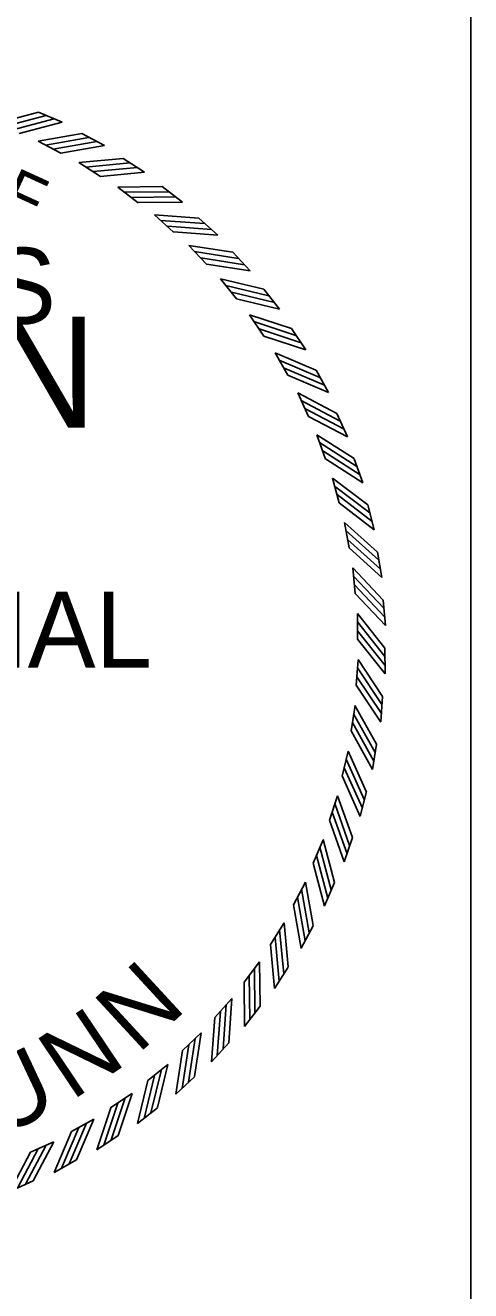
# Model space of a CAD drawing. Extents: x 0 to 1228740, y 0 to 152440.
# Drawn here: x 32.511 to 33.423, y 17.743 to 20.334 of the extents above; entities that cross this region are included whole.
import ezdxf

# ---------------------------------------------------------------- set-up
doc = ezdxf.new("R2010")
doc.units = 0
for name, color, linetype in [('R_Border', 7, 'Continuous'), ('R_Draft', 7, 'Continuous'), ('STAMP', 7, 'Continuous')]:
    doc.layers.add(name, color=color, linetype=linetype)

msp = doc.modelspace()

# ---------------------------------------------------------------- linework, layer by layer
at = {"layer": 'R_Border'}
msp.add_line((33.4231, 0.5768), (33.4231, 21.4232), dxfattribs=at)
at = {"layer": 'STAMP'}
for p, q in [((32.5379, 20.1563), (32.5861, 20.1357)), ((32.6265, 20.1125), (32.6728, 20.088)), ((32.5372, 20.0967), (32.5836, 20.0721)), ((32.7111, 20.0615), (32.7552, 20.0332)), ((32.6208, 20.0531), (32.665, 20.0248)), ((32.7005, 20.0028), (32.7422, 19.9709)), ((32.7912, 20.0037), (32.8328, 19.9719)), ((32.7758, 19.946), (32.8147, 19.9108)), ((32.8662, 19.9395), (32.9051, 19.9043)), ((32.8461, 19.8833), (32.882, 19.845)), ((32.9357, 19.8693), (32.9716, 19.831)), ((32.911, 19.8149), (32.9437, 19.7738)), ((32.9992, 19.7936), (33.0317, 19.7525)), ((32.9701, 19.7415), (32.9992, 19.6978)), ((33.0562, 19.7129), (33.0852, 19.6693)), ((33.0229, 19.6634), (33.0483, 19.6174)), ((33.1063, 19.6278), (33.1316, 19.5819)), ((33.069, 19.5812), (33.0906, 19.5333)), ((33.1492, 19.5388), (33.1707, 19.491)), ((33.1082, 19.4954), (33.1257, 19.4459)), ((33.1847, 19.4466), (33.2021, 19.3972)), ((33.1402, 19.4068), (33.1536, 19.356)), ((33.2124, 19.3518), (33.2257, 19.3011)), ((33.1648, 19.3157), (33.1739, 19.264)), ((33.2321, 19.255), (33.2412, 19.2034)), ((33.1818, 19.223), (33.1866, 19.1707)), ((33.2438, 19.1569), (33.2487, 19.1047)), ((33.191, 19.1292), (33.1915, 19.0767)), ((33.2474, 19.0582), (33.2479, 19.0058)), ((33.1925, 19.0349), (33.1886, 18.9826)), ((33.2428, 18.9595), (33.239, 18.9073)), ((33.1862, 18.9409), (33.178, 18.889)), ((33.1721, 18.8477), (33.1597, 18.7966)), ((33.2301, 18.8616), (33.222, 18.8098)), ((33.2094, 18.765), (33.197, 18.7141)), ((33.1504, 18.7559), (33.1338, 18.7061)), ((33.1212, 18.6663), (33.1005, 18.618)), ((33.1807, 18.6705), (33.1641, 18.6208)), ((33.0846, 18.5794), (33.0601, 18.533)), ((33.1443, 18.5786), (33.1237, 18.5305)), ((33.0411, 18.4958), (33.0128, 18.4516)), ((33.1005, 18.4901), (33.076, 18.4438)), ((32.9908, 18.4161), (32.9589, 18.3743)), ((33.0495, 18.4055), (33.0212, 18.3614)), ((32.934, 18.3408), (32.8988, 18.3018)), ((32.9917, 18.3254), (32.9599, 18.2838)), ((32.8713, 18.2705), (32.833, 18.2345)), ((32.9274, 18.2504), (32.8923, 18.2115)), ((32.8029, 18.2055), (32.7618, 18.1729)), ((32.8572, 18.1809), (32.819, 18.145)), ((32.7294, 18.1465), (32.6857, 18.1174)), ((32.7815, 18.1174), (32.7405, 18.0848)), ((32.6513, 18.0937), (32.6054, 18.0683)), ((32.5691, 18.0475), (32.5212, 18.026)), ((32.7009, 18.0604), (32.6573, 18.0314)), ((32.6157, 18.0103), (32.5699, 17.9849)), ((32.5268, 17.9674), (32.479, 17.9459))]:
    msp.add_line(p, q, dxfattribs=at)
for points in [[(32.4502, 20.1332), (32.5379, 20.1563)], [(32.4656, 20.1264), (32.5533, 20.1495)], [(32.4825, 20.1196), (32.5702, 20.1428)], [(32.4985, 20.1126), (32.5862, 20.1357)], [(32.5371, 20.0967), (32.6264, 20.1125)], [(32.5519, 20.0886), (32.6412, 20.1045)], [(32.5682, 20.0805), (32.6575, 20.0963)], [(32.5836, 20.0722), (32.6728, 20.088)], [(32.6207, 20.0531), (32.711, 20.0615)], [(32.6348, 20.0439), (32.7251, 20.0523)], [(32.6504, 20.0344), (32.7406, 20.0428)], [(32.665, 20.0248), (32.7553, 20.0333)], [(32.7004, 20.0028), (32.7911, 20.0037)], [(32.7137, 19.9924), (32.8044, 19.9933)], [(32.7284, 19.9817), (32.8191, 19.9826)], [(32.7422, 19.971), (32.8329, 19.9719)], [(32.7757, 19.9461), (32.8661, 19.9395)], [(32.7881, 19.9346), (32.8785, 19.9281)], [(32.8019, 19.9227), (32.8923, 19.9162)], [(32.8147, 19.9109), (32.9052, 19.9043)], [(32.846, 19.8833), (32.9356, 19.8693)], [(32.8575, 19.8709), (32.947, 19.8569)], [(32.8702, 19.8579), (32.9598, 19.8439)], [(32.882, 19.845), (32.9716, 19.831)], [(32.911, 19.815), (32.9991, 19.7936)], [(32.9213, 19.8016), (33.0094, 19.7803)], [(32.9329, 19.7876), (33.0211, 19.7663)], [(32.9437, 19.7739), (33.0318, 19.7525)], [(32.97, 19.7415), (33.0561, 19.7129)], [(32.9792, 19.7274), (33.0653, 19.6988)], [(32.9897, 19.7124), (33.0757, 19.6839)], [(32.9992, 19.6978), (33.0853, 19.6693)], [(33.0228, 19.6634), (33.1062, 19.6278)], [(33.0308, 19.6485), (33.1142, 19.613)], [(33.04, 19.6328), (33.1234, 19.5972)], [(33.0483, 19.6175), (33.1317, 19.5819)], [(33.069, 19.5812), (33.1491, 19.5389)], [(33.0757, 19.5657), (33.1559, 19.5234)], [(33.0836, 19.5493), (33.1637, 19.507)], [(33.0906, 19.5333), (33.1708, 19.491)], [(33.1082, 19.4955), (33.1846, 19.4467)], [(33.1136, 19.4795), (33.1901, 19.4307)], [(33.1201, 19.4625), (33.1965, 19.4137)], [(33.1258, 19.446), (33.2022, 19.3972)], [(33.1402, 19.4068), (33.2123, 19.3518)], [(33.1443, 19.3905), (33.2164, 19.3355)], [(33.1493, 19.3729), (33.2214, 19.318)], [(33.1536, 19.356), (33.2257, 19.3011)], [(33.1647, 19.3158), (33.2321, 19.2551)], [(33.1675, 19.2992), (33.2348, 19.2384)], [(33.1711, 19.2813), (33.2384, 19.2206)], [(33.1739, 19.2641), (33.2413, 19.2034)], [(33.1817, 19.2231), (33.2438, 19.157)], [(33.1831, 19.2063), (33.2452, 19.1402)], [(33.1852, 19.1882), (33.2473, 19.1221)], [(33.1866, 19.1708), (33.2487, 19.1047)], [(33.191, 19.1293), (33.2474, 19.0583)], [(33.191, 19.1124), (33.2474, 19.0414)], [(33.1915, 19.0942), (33.2479, 19.0232)], [(33.1915, 19.0767), (33.2479, 19.0058)], [(33.1924, 19.035), (33.2428, 18.9596)], [(33.1901, 19), (33.2405, 18.9246)], [(33.191, 19.0182), (33.2414, 18.9428)], [(33.1887, 18.9826), (33.239, 18.9072)], [(33.1833, 18.9243), (33.2273, 18.845)], [(33.1861, 18.941), (33.2301, 18.8617)], [(33.1809, 18.9063), (33.2249, 18.827)], [(33.178, 18.8891), (33.222, 18.8098)], [(33.1721, 18.8477), (33.2093, 18.7651)], [(33.1679, 18.8314), (33.2052, 18.7487)], [(33.1597, 18.7967), (33.197, 18.714)], [(33.164, 18.8136), (33.2013, 18.731)], [(33.1449, 18.7401), (33.1752, 18.6546)], [(33.1504, 18.756), (33.1807, 18.6706)], [(33.1395, 18.7227), (33.1698, 18.6372)], [(33.1338, 18.7061), (33.1642, 18.6207)], [(33.1211, 18.6664), (33.1443, 18.5787)], [(33.1076, 18.634), (33.1307, 18.5464)], [(33.1144, 18.6509), (33.1375, 18.5633)], [(33.1006, 18.6181), (33.1237, 18.5304)], [(33.0766, 18.5646), (33.0924, 18.4754)], [(33.0846, 18.5795), (33.1005, 18.4902)], [(33.0601, 18.533), (33.076, 18.4437)], [(33.0684, 18.5484), (33.0843, 18.4591)], [(33.0318, 18.4818), (33.0403, 18.3915)], [(33.0411, 18.4959), (33.0495, 18.4056)], [(33.0224, 18.4662), (33.0308, 18.3759)], [(33.0128, 18.4516), (33.0212, 18.3613)], [(32.9804, 18.4029), (32.9813, 18.3122)], [(32.9908, 18.4162), (32.9917, 18.3255)], [(32.9589, 18.3744), (32.9599, 18.2837)], [(32.9697, 18.3881), (32.9706, 18.2975)], [(32.9226, 18.3285), (32.916, 18.238)], [(32.934, 18.3409), (32.9275, 18.2505)], [(32.8989, 18.3019), (32.8923, 18.2114)], [(32.9107, 18.3147), (32.9041, 18.2243)], [(32.8713, 18.2705), (32.8573, 18.181)], [(32.8459, 18.2464), (32.8319, 18.1568)], [(32.8589, 18.2591), (32.8449, 18.1695)], [(32.833, 18.2345), (32.819, 18.145)], [(32.7896, 18.1953), (32.7683, 18.1071)], [(32.8029, 18.2056), (32.7816, 18.1175)], [(32.7618, 18.1729), (32.7405, 18.0848)], [(32.7756, 18.1836), (32.7542, 18.0955)], [(32.7295, 18.1466), (32.7009, 18.0605)], [(32.6858, 18.1174), (32.6572, 18.0313)], [(32.7004, 18.1269), (32.6718, 18.0409)], [(32.7153, 18.1373), (32.6868, 18.0513)], [(32.6514, 18.0938), (32.6158, 18.0104)], [(32.6054, 18.0683), (32.5699, 17.9849)], [(32.6208, 18.0766), (32.5852, 17.9932)], [(32.6365, 18.0857), (32.601, 18.0023)], [(32.5537, 18.0408), (32.5114, 17.9607)], [(32.5692, 18.0476), (32.5268, 17.9674)], [(32.5213, 18.026), (32.479, 17.9458)], [(32.5373, 18.033), (32.4949, 17.9528)]]:
    msp.add_lwpolyline(points, dxfattribs=at)

# ---------------------------------------------------------------- texts
at = {"layer": 'R_Draft'}
msp.add_text('SUBJECT TO REVISION', height=0.227432, rotation=0, dxfattribs=at).set_placement((29.2271, 19.5102))
at = {"layer": 'STAMP'}
for s, height, rotation, p in [('F', 0.0953, 335.3628, (32.454, 19.9576)), ('N', 0.1448, 42.6817, (32.7412, 18.2254)), ('N', 0.1448, 33.9264, (32.6056, 18.1304)), ('U', 0.1448, 25.1712, (32.4571, 18.0571))]:
    msp.add_text(s, height=height, rotation=rotation, dxfattribs=at).set_placement(p)
for s, height, p in [('ARKANSAS', 0.15559, (31.4406, 19.7229)), ('PROFESSIONAL', 0.155594, (31.1517, 19.0188))]:
    msp.add_text(s, height=height, dxfattribs=at).set_placement(p)

doc.saveas('drawing.dxf')
